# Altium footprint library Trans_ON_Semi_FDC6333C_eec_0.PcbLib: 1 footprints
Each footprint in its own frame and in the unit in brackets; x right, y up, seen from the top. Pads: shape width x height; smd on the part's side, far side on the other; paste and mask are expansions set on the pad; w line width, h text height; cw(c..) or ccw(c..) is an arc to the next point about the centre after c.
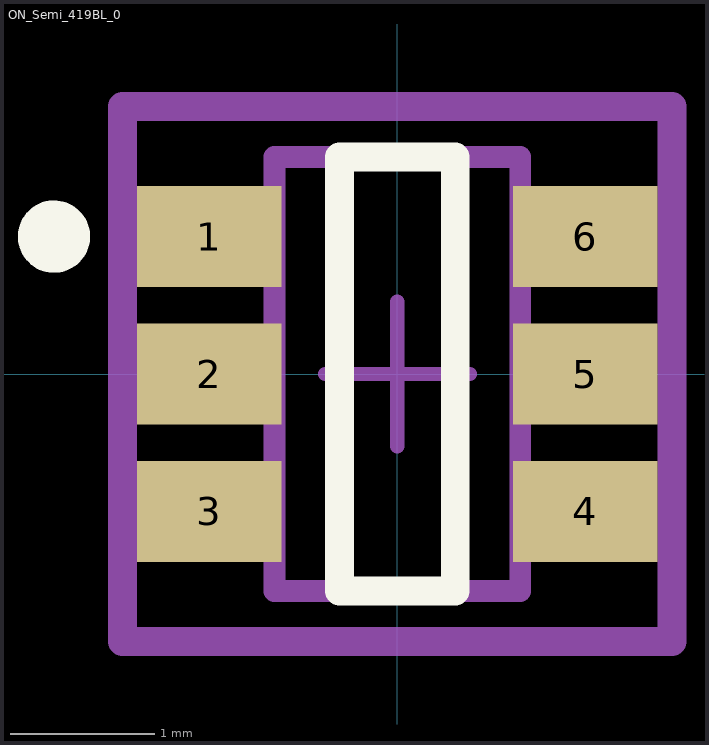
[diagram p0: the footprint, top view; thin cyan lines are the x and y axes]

## ON_Semi_419BL_0 [mm]
pads (6):
  rect 1x0.7 smd paste+0 mask+0: 1(-1.3,0.95) 2(-1.3,0) 3(-1.3,-0.95) 4(1.3,-0.95) 5(1.3,0) 6(1.3,0.95)
Top Overlay:
  circle w0.25: c-2.375,0.95 r0.125
  lines w0.2: -0.4,-1.5 0.4,-1.5 0.4,1.5 -0.4,1.5 -0.4,-1.5
Mechanical 10:
  lines w0.2: -1.9,-1.85 1.9,-1.85 1.9,1.85 -1.9,1.85 -1.9,-1.85
  text ".Designator" at 0,0 h1
Mechanical 12:
  lines w0.15: -0.85,-1.5 0.85,-1.5 0.85,1.5 -0.85,1.5 -0.85,-1.5
Mechanical 15:
  lines w0.1: -0.5,0 0.5,0 ; 0,-0.5 0,0.5
  lines w0.2: -1.9,-1.85 1.9,-1.85 1.9,1.85 -1.9,1.85 -1.9,-1.85
3D body "Trans_ON_Semi_FDC6333C_eec.STEP": height 0.25, standoff 0, extent -1.9,-1.85 1.9,1.85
